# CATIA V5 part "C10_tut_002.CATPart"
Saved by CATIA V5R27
Part number: Part1
Bounding box of the stored display mesh (mm): x -105 to 105, y -154.989 to 550, z -23.302 to 23.303
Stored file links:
  E:\_Deepak\2017_Deepak\CATIA\Resources\Tutorial Files\Tutorials\c10_catia_v5_6r2016_tut\C10_tut_002.CATPart
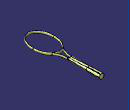
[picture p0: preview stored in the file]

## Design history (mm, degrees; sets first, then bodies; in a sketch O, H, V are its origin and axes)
Body1 (main body)
  Sketch1 on xy-plane, origin (0, 0, 0), H (1, 0, 0), V (0, 1, 0)
    ellipse A1 centre (0, 0) semi-axes 100, 150 rotation 0
    point P1 (100, 0)
    point P2 (-100, 0)
    "Radius" A1 = 100
    "Radius" A1 = 150
    "Radius" A1 = 100 (reference)
    coincidence: P1 H, A1 P1, P2 A1, P2 H
    perpendicularity: A1 V
  Sketch2 on zx-plane, origin (0, 0, 0), H (-1, 0, 0), V (0, 0, 1)
    point P1 (100, 0)
    ellipse A1 centre (100, 0) semi-axes 10, 5 rotation 270
    reference projected point E1 (100, 0) from Sketch1.P2
    "Radius" A1 = 10
    "Radius" A1 = 5
    coincidence: P1 H, P1 E1
    vertical: A1 V
  Sweep1: type Unspec, Profile Sketch2, Guide Sketch1.A1
  Sketch3 on xy-plane, origin (0, 0, 0), H (1, 0, 0), V (0, 1, 0)
    line L1 (15, 245) -> (15, 250)
    point P2 (15, 250)
    arc A1 centre (215, 245) radius 200 from (15, 245) to (55, 125) ccw
    point P4 (55, 125)
    distance L1 V = 15
    distance P2 H = 250
    radius A1 = 200
    distance P4 V = 55
    distance P4 H = 125
    tangency: L1 A1
  Plane1: type Normal, Curve Sketch3, RefPoint Sketch3.P2, Ratio 0
  Sketch4 on Plane1, origin (0, 250, 0), H (1, 0, 0), V (0, 0, 1)
    point P1 (15, 0)
    ellipse A1 centre (15, 0) semi-axes 8.75, 4.5 rotation 270
    reference projected point E1 (15, 0) from Sketch3.P2
    "Radius" A1 = 8.75
    "Radius" A1 = 4.5
    coincidence: P1 H, P1 E1
  Sweep2: type Unspec, Profile Sketch4, Guide Sketch3
  Symmetry1: ToTransfor Sweep2, Reference yz-plane
  Trim1: Trimmed (Symmetry1; Sweep1)
  Trim2: Trimmed (Sweep2; Trim1)
  Sketch5 on Plane1, origin (0, 250, 0), H (1, 0, 0), V (0, 0, 1)
    projected curve E1 from edge of Sweep2
    projected curve E2 from edge of Sweep2
    projected curve E3 from edge of Symmetry1
    projected curve E4 from edge of Symmetry1
    line L1 (11.75, 6.052) -> (-11.75, 6.052)
    point P1 (11.75, 6.052)
    point P2 (-11.75, 6.052)
    reference intersected line E5 through (0, 0) direction (-1, 0) from xy-plane
    point P5 (-11.75, -6.052)
    point P6 (11.75, -6.052)
    line L2 (11.75, -6.052) -> (-11.75, -6.052)
    point P7 (-11.75, -6.052)
    point P8 (11.75, -6.052)
    length L1 = 23.5
    coincidence: P1 E1, P2 E3, L2 P7, L2 P8
    horizontal: L1 H
    symmetry: P2 P5 E5, P1 P6 E5, L1 L2 E5
  Plane2: type Offset, RefPlane zx-plane, Offset 425
  Sketch6 on Plane2, origin (0, 425, 0), H (-1, 0, 0), V (0, 0, 1)
    ellipse A1 centre (0, 0) semi-axes 22.5, 20 rotation 0
    point P1 (22.5, 0)
    point P2 (-11.75, 17.0562)
    point P3 (11.75, 17.0562)
    point P4 (11.75, -17.0562)
    point P5 (-11.75, -17.0562)
    "Radius" A1 = 22.5
    "Radius" A1 = 20
    distance P2 P3 = 23.5
    distance P2 V = 11.75
    distance P5 V = 11.75
    distance P4 P5 = 23.5
    distance P3 P4 = 34.1124
    coincidence: P1 H, A1 P1, P2 A1, P3 A1, P4 A1, P5 A1
  Loft1: Sections (Sketch5; Sketch6.A1), SectionCouplingPoints ({coupling CouplingPoints (vertex [element of Sketch5 | element of Sketch5]; Sketch6.P2)}; {coupling CouplingPoints (vertex [element of Sketch5 | element of Sketch5]; Sketch6.P5)}; {coupling CouplingPoints (vertex [element of Sketch5 | element of Sketch5]; Sketch6.P3)}; {coupling CouplingPoints (vertex [element of Sketch5 | element of Sketch5]; Sketch6.P4)})
  Plane3: type Offset, RefPlane zx-plane, Offset 550
  Sketch7 on Plane3, origin (0, 550, 0), H (-1, 0, 0), V (0, 0, 1)
    circle A1 centre (0, 0) radius 22.5
    radius A1 = 22.5
  Blend1: StartLimit {blendlimit Curve Sketch6.A1, Point {extremum Reference Sketch6.A1, Direction (1, 2, 3)}, Support Loft1}, EndLimit {blendlimit Curve Sketch7, Point {extremum Reference Sketch7, Direction (1, 2, 3)}}
  Fill1: Boundary edge of Blend1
